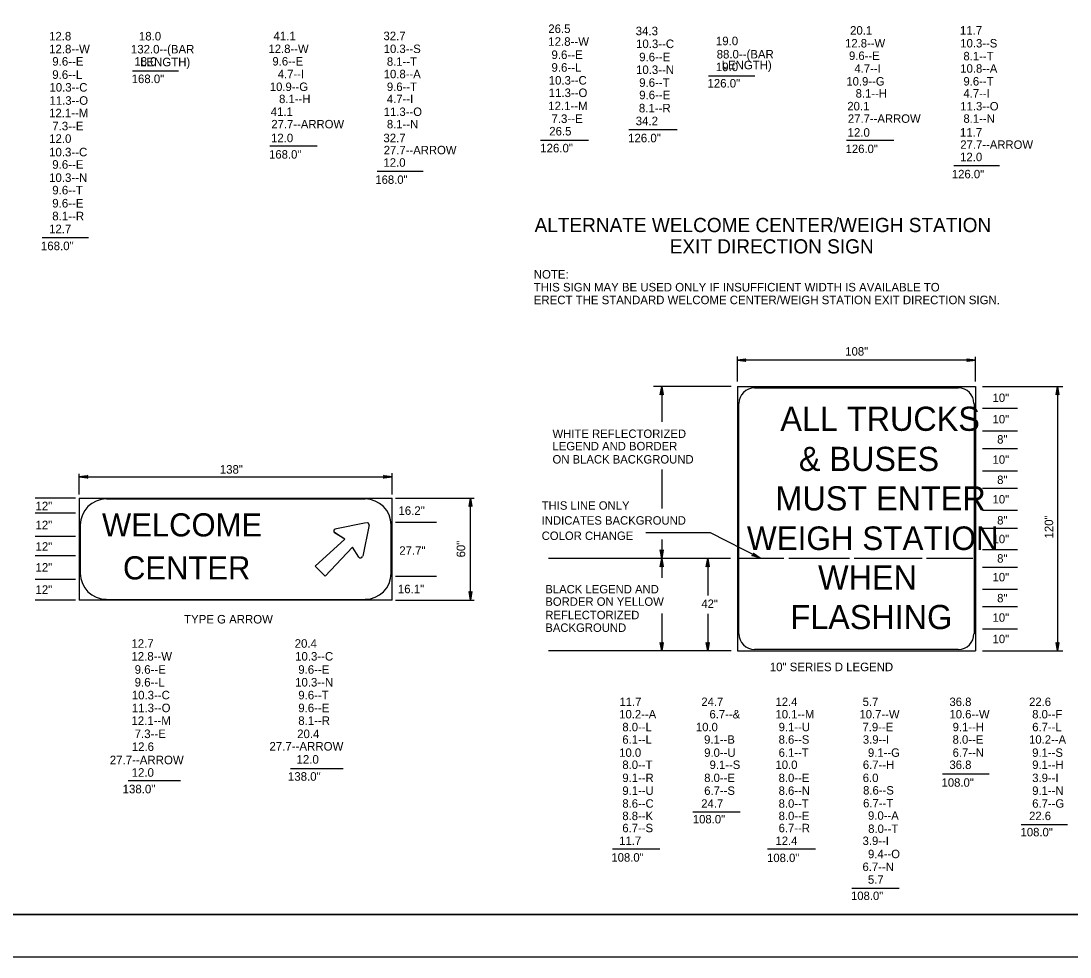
# Model space of a CAD drawing. Extents: x 2189973 to 2192941, y 2147557 to 2151454.
# Drawn here: x 2190680 to 2191890, y 2147557 to 2148636 of the extents above; entities that cross this region are included whole.
import ezdxf

# ---------------------------------------------------------------- set-up
doc = ezdxf.new("R2010")
doc.units = 0
for name, color, linetype in [('Default', 7, 'Continuous'), ('Level 2', 7, 'Continuous'), ('PLT-BNDY', 7, 'Continuous')]:
    doc.layers.add(name, color=color, linetype=linetype)

# ---------------------------------------------------------------- blocks, each defined once
blk = doc.blocks.new('RARROW')
at = {"layer": 'Default'}
blk.add_lwpolyline([(-18.156, 2.28), (-17.479, 0.966), (0, 0), (-18.156, 2.28), (-19.086, 3.077), (0, 0), (-17.465, -0.864), (-18.103, -2.164), (0, 0), (-19.086, -3.033), (-18.103, -2.164)], dxfattribs=at)

msp = doc.modelspace()

# ---------------------------------------------------------------- linework, layer by layer
at = {"layer": 'Default'}
for p, q in [((2190808.9, 2148579), (2190862.2, 2148579)), ((2191473.3, 2148573.2), (2191526.6, 2148573.2)), ((2191381.2, 2148511.3), (2191437, 2148511.3)), ((2190967.4, 2148492.5), (2191021.9, 2148492.5)), ((2191279.6, 2148499.1), (2191334.6, 2148499.1)), ((2191632.2, 2148498.9), (2191686.8, 2148498.9)), ((2191756.1, 2148469.7), (2191808.8, 2148469.7)), ((2191091.3, 2148463.4), (2191144, 2148463.4)), ((2190704.9, 2148386.8), (2190758.2, 2148386.8)), ((2190747.5, 2148090.3), (2190747.5, 2148114)), ((2190747.5, 2148110.7), (2191108.4, 2148110.7)), ((2191108.4, 2148090.3), (2191108.4, 2148114.8)), ((2190743.4, 2148086.2), (2190696.9, 2148086.2)), ((2190747.5, 2148086.2), (2191108.4, 2148086.2)), ((2190747.5, 2148086.2), (2190747.5, 2147968.5)), ((2191077.2, 2148085), (2190779.1, 2148085)), ((2191108.4, 2147968.5), (2191108.4, 2148086.2)), ((2191112.1, 2148086.2), (2191140.4, 2148086.2)), ((2191112.1, 2148086.2), (2191202.9, 2148086.2)), ((2191198.8, 2147968.5), (2191198.8, 2148086.2)), ((2190743.4, 2148068.6), (2190696.9, 2148068.6)), ((2191042.4, 2148050.5), (2191078.5, 2148057.9)), ((2191042.4, 2148050.5), (2191078.5, 2148057.9)), ((2191112.1, 2148058.3), (2191159.5, 2148058.3)), ((2190748.8, 2148055.1), (2190748.8, 2147999.3)), ((2191053.9, 2148038.7), (2191042, 2148046.4)), ((2191053.9, 2148038.7), (2191042, 2148046)), ((2191081.8, 2148055.1), (2191074.4, 2148019)), ((2191081.8, 2148055.1), (2191074.4, 2148019)), ((2191107.2, 2147999.3), (2191107.2, 2148055.1)), ((2190743.4, 2148041.9), (2190696.9, 2148041.9)), ((2191019.8, 2148007.5), (2191053.9, 2148038.7)), ((2191019.8, 2148007.5), (2191053.9, 2148038.7)), ((2191062.5, 2148029.6), (2191031.3, 2147996)), ((2191062.5, 2148029.6), (2191031.3, 2147996)), ((2191069.9, 2148018.1), (2191062.5, 2148029.6)), ((2191069.9, 2148018.1), (2191062.5, 2148029.6)), ((2190743.4, 2148019.4), (2190696.9, 2148019.4)), ((2191031.3, 2147996), (2191019.8, 2148007.5)), ((2191031.3, 2147996), (2191019.8, 2148007.5)), ((2190743.4, 2147992.3), (2190696.9, 2147992.3)), ((2191112.1, 2147996), (2191159.5, 2147996)), ((2190743.4, 2147968.5), (2190696.9, 2147968.5)), ((2191108.4, 2147968.5), (2190747.5, 2147968.5)), ((2190779.1, 2147969.3), (2191077.2, 2147969.3)), ((2191112.1, 2147968.5), (2191202.9, 2147968.5)), ((2190991.1, 2147774.4), (2191051.8, 2147774.4)), ((2190804.1, 2147760.3), (2190864.4, 2147760.3)), ((2192683.2, 2147606), (2190104.5, 2147606)), ((2190104.5, 2147606), (2192027, 2147606))]:
    msp.add_line(p, q, dxfattribs=at)
for centre, radius, start, end in [((2190778.8, 2148055.1), 30, 90, 180), ((2191077.2, 2148055.1), 30, 0, 90), ((2191079.5, 2148055.5), 2.25, 348.2602, 101.7398), ((2191079.5, 2148055.5), 2.25, 348.2602, 101.7398), ((2191043.3, 2148048), 2.25, 101.7398, 236.6838), ((2191043.3, 2148048), 2.25, 101.7398, 236.6838), ((2191071.9, 2148019.4), 2.25, 213.3162, 348.2602), ((2191071.9, 2148019.4), 2.25, 213.3162, 348.2602), ((2190778.8, 2147999.4), 30, 180, 270), ((2191077.2, 2147999.4), 30, 270, 0)]:
    msp.add_arc(centre, radius, start, end, dxfattribs=at)
at = {"layer": 'Level 2'}
for p, q in [((2191506.5, 2148220.7), (2191506.5, 2148249.4)), ((2191780.9, 2148245.3), (2191506.5, 2148245.3)), ((2191780.9, 2148220.7), (2191780.9, 2148249)), ((2191499.2, 2148215), (2191409.8, 2148215)), ((2191419.2, 2148215), (2191419.2, 2148174)), ((2191506.5, 2148215), (2191780.9, 2148215)), ((2191506.5, 2148215), (2191506.5, 2147909.9)), ((2191780.9, 2148215), (2191780.9, 2147909.9)), ((2191789.1, 2148215), (2191881.8, 2148215)), ((2191875.6, 2148215), (2191875.6, 2147909.9)), ((2191526.2, 2148213.4), (2191761.2, 2148213.4)), ((2191508.2, 2147929.6), (2191508.2, 2148195.3)), ((2191779.3, 2148195.3), (2191779.3, 2147929.6)), ((2191789.1, 2148190), (2191829.3, 2148190)), ((2191789.1, 2148163.7), (2191829.3, 2148163.7)), ((2191789.1, 2148143.2), (2191829.3, 2148143.2)), ((2191419.2, 2148119.2), (2191419.2, 2148074.3)), ((2191789.1, 2148117.4), (2191829.3, 2148117.4)), ((2191789.1, 2148097.7), (2191829.3, 2148097.7)), ((2191789.1, 2148072.3), (2191829.3, 2148072.3)), ((2191475.4, 2148046), (2191401, 2148046)), ((2191532.8, 2148016.9), (2191475.4, 2148046)), ((2191789.1, 2148051.4), (2191829.3, 2148051.4)), ((2191419.2, 2148038.3), (2191419.2, 2148016.5)), ((2191789.1, 2148026.8), (2191829.3, 2148026.8)), ((2191498.5, 2148016.5), (2191288.8, 2148016.5)), ((2191419.2, 2148016.5), (2191419.2, 2147994)), ((2191472.2, 2148016.5), (2191472.2, 2147973.9)), ((2191559.9, 2148016.5), (2191509, 2148016.5)), ((2191635.7, 2148016.5), (2191565.6, 2148016.5)), ((2191719.4, 2148016.5), (2191641.1, 2148016.5)), ((2191778, 2148016.5), (2191724.7, 2148016.5)), ((2191789.1, 2148006.3), (2191829.3, 2148006.3)), ((2191789.1, 2147981.2), (2191829.3, 2147981.2)), ((2191789.1, 2147961.1), (2191829.3, 2147961.1)), ((2191419.2, 2147952.9), (2191419.2, 2147909.9)), ((2191472.2, 2147952.5), (2191472.2, 2147909.9)), ((2191789.1, 2147935.3), (2191829.3, 2147935.3)), ((2191499.2, 2147909.9), (2191288.8, 2147909.9)), ((2191506.5, 2147909.9), (2191780.9, 2147909.9)), ((2191761.2, 2147911.5), (2191526.2, 2147911.5)), ((2191789.1, 2147909.9), (2191881.8, 2147909.9)), ((2191742.8, 2147768), (2191796.9, 2147768)), ((2191455, 2147724.4), (2191509.6, 2147724.4)), ((2191833.5, 2147709.7), (2191887, 2147709.7)), ((2191362.4, 2147681.5), (2191417, 2147681.5)), ((2191541.1, 2147681.5), (2191596.7, 2147681.5)), ((2191638.5, 2147636.3), (2191693.1, 2147636.3))]:
    msp.add_line(p, q, dxfattribs=at)
for centre, start, end in [((2191526.2, 2148195.3), 90, 180), ((2191761.2, 2148195.3), 0, 90), ((2191526.2, 2147929.6), 180, 270), ((2191761.2, 2147929.6), 270, 360)]:
    msp.add_arc(centre, 18, start, end, dxfattribs=at)
at = {"layer": 'PLT-BNDY'}
msp.add_lwpolyline([(2189973.2, 2149505.6), (2192732.4, 2149505.6), (2192732.4, 2147556.8), (2189973.2, 2147556.8)], close=True, dxfattribs=at)

# ---------------------------------------------------------------- block references
at = {"layer": 'Default', "xscale": 0.515679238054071, "yscale": 0.5369477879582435}
for p, rotation in [((2190747.5, 2148110.7), 180), ((2191198.8, 2148086.2), 89.99999999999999), ((2191198.8, 2147968.5), -90.00000000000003)]:
    msp.add_blockref('RARROW', p, dxfattribs=dict(at, rotation=rotation))
msp.add_blockref('RARROW', (2191108.4, 2148110.7), dxfattribs=at)
at = {"layer": 'Level 2', "xscale": 0.515679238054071, "yscale": 0.5369477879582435}
for p, rotation in [((2191506.5, 2148245.3), 180), ((2191419.2, 2148215), 89.99999999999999), ((2191875.6, 2148215), 89.99999999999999), ((2191419.2, 2148016.5), -90.00000000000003), ((2191532.8, 2148016.9), -26.538667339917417), ((2191419.2, 2148016.5), 89.99999999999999), ((2191472.2, 2148016.5), 89.99999999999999), ((2191419.2, 2147909.9), -90.00000000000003), ((2191472.2, 2147909.9), -90.00000000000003), ((2191875.6, 2147909.9), -90.00000000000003)]:
    msp.add_blockref('RARROW', p, dxfattribs=dict(at, rotation=rotation))
msp.add_blockref('RARROW', (2191780.9, 2148245.3), dxfattribs=at)

# ---------------------------------------------------------------- texts
at = {"layer": 'Default'}
for s, height, p in [('26.5   ', 9.84, (2191288.4, 2148622.6)), ('34.3   ', 9.89, (2191389.2, 2148620)), ('20.1      ', 9.84, (2191636.4, 2148620.7)), ('11.7       ', 9.842, (2191763.1, 2148620.7)), ('12.8   ', 9.84, (2190712.8, 2148614)), ('18.0               ', 9.842, (2190816.4, 2148614)), ('41.1      ', 9.84, (2190971.6, 2148614.3)), ('32.7       ', 9.842, (2191098.3, 2148614.3)), ('12.8--W', 9.89, (2191288.4, 2148607.8)), ('10.3--C', 9.84, (2191389.6, 2148605.2)), ('19.0               ', 9.842, (2191481.7, 2148608.5)), (' 12.8--W    ', 9.732, (2191627, 2148605.9)), ('10.3--S    ', 9.732, (2191763.5, 2148605.9)), ('12.8--W', 9.89, (2190712.8, 2148599.2)), ('132.0--(BAR', 9.842, (2190807.2, 2148599)), (' 12.8--W    ', 9.732, (2190962.2, 2148599.5)), ('10.3--S    ', 9.732, (2191098.7, 2148599.5)), (' 9.6--E', 9.89, (2191288.4, 2148592.6)), ('88.0--(BAR', 9.84, (2191482.6, 2148593.2)), ('  9.6--E     ', 9.732, (2191627.9, 2148591.5)), (' 9.6--E', 9.89, (2190712.8, 2148584.9)), (' 18.0               ', 9.842, (2190807.5, 2148584.9)), ('         LENGTH)', 9.842, (2190784.9, 2148584.2)), ('  9.6--E     ', 9.732, (2190963.1, 2148585.1)), (' 8.1--T    ', 9.732, (2191098.7, 2148584.8)), (' 9.6--E', 9.84, (2191389.6, 2148590)), ('         LENGTH)', 9.842, (2191455.4, 2148580.7)), (' 8.1--T    ', 9.732, (2191763.5, 2148591.1)), (' 9.6--L', 9.89, (2190712.8, 2148569.7)), (' 4.7--I    ', 9.732, (2190972.9, 2148570.4)), ('10.8--A    ', 9.732, (2191098.7, 2148570.4)), (' 9.6--L', 9.89, (2191288.4, 2148577.9)), ('10.3--N', 9.84, (2191389.6, 2148575.3)), ('19.0               ', 9.842, (2191481.7, 2148578.6)), (' 4.7--I    ', 9.732, (2191637.8, 2148576.8)), ('10.8--A    ', 9.732, (2191763.5, 2148576.8)), ('10.3--C', 9.84, (2190713.2, 2148555)), ('168.0"              ', 9.842, (2190808, 2148564.8)), (' 10.9--G    ', 9.732, (2190963.7, 2148555.7)), (' 9.6--T    ', 9.732, (2191098.7, 2148555.7)), ('10.3--C', 9.84, (2191288.9, 2148563.1)), (' 9.6--T', 9.84, (2191389.6, 2148560.5)), ('126.0"', 9.84, (2191472, 2148559.7)), (' 10.9--G    ', 9.732, (2191628.5, 2148562)), (' 9.6--T    ', 9.732, (2191763.5, 2148562)), ('11.3--O', 9.84, (2191288.9, 2148548.7)), (' 9.6--E', 9.84, (2191389.6, 2148546.2)), (' 8.1--H    ', 9.732, (2191639.2, 2148548.1)), (' 4.7--I    ', 9.732, (2191763.5, 2148548.1)), ('11.3--O', 9.84, (2190713.2, 2148539.8)), (' 8.1--H    ', 9.732, (2190974.4, 2148541.7)), (' 4.7--I    ', 9.732, (2191098.7, 2148541.7)), ('12.1--M', 9.84, (2191288.4, 2148533.6)), (' 8.1--R', 9.89, (2191389.2, 2148531)), (' 20.1       ', 9.842, (2191629.5, 2148533.3)), ('11.3--O    ', 9.732, (2191763.5, 2148533.3)), ('12.1--M', 9.84, (2190712.8, 2148525.4)), (' 41.1       ', 9.842, (2190964.7, 2148526.9)), ('11.3--O    ', 9.732, (2191098.7, 2148526.9)), (' 7.3--E', 9.89, (2191288.4, 2148518.8)), (' 27.7--ARROW', 9.732, (2191630.3, 2148519)), (' 8.1--N    ', 9.732, (2191763.5, 2148519)), (' 7.3--E', 9.89, (2190712.8, 2148510.3)), (' 27.7--ARROW', 9.732, (2190965.5, 2148512.6)), (' 8.1--N    ', 9.732, (2191098.7, 2148512.6)), ('34.2   ', 9.89, (2191389.2, 2148516.2)), ('12.0   ', 9.84, (2190712.9, 2148495.9)), (' 12.0       ', 9.842, (2190965, 2148496.6)), ('32.7       ', 9.842, (2191098.3, 2148496.6)), ('26.5', 9.84, (2191289.5, 2148504.4)), ('126.0"', 9.89, (2191380.4, 2148496.5)), (' 12.0       ', 9.842, (2191629.9, 2148503)), ('11.7       ', 9.842, (2191763.1, 2148503)), ('27.7--ARROW', 9.732, (2191098.7, 2148482.7)), ('126.0"   ', 9.89, (2191279.1, 2148484.9)), ('126.0"       ', 9.732, (2191631.3, 2148484.1)), ('27.7--ARROW', 9.732, (2191763.5, 2148489)), ('10.3--C', 9.89, (2190712.8, 2148480.3)), ('168.0"       ', 9.732, (2190966.5, 2148477.7)), ('12.0', 9.84, (2191763.2, 2148474.7)), (' 9.6--E', 9.89, (2190712.8, 2148466)), ('12.0', 9.84, (2191098.3, 2148468.3)), ('10.3--N', 9.89, (2190712.8, 2148450.8)), ('168.0"       ', 9.732, (2191089, 2148448.6)), ('126.0"       ', 9.732, (2191753.8, 2148455)), (' 9.6--T', 9.89, (2190712.8, 2148436.4)), (' 9.6--E', 9.89, (2190712.8, 2148421.3)), (' 8.1--R', 9.89, (2190712.8, 2148406.5)), ('ALTERNATE WELCOME CENTER/WEIGH STATION', 16.404, (2191272.6, 2148392.9)), ('12.7   ', 9.84, (2190712.8, 2148391.7)), ('EXIT DIRECTION SIGN', 16.404, (2191428.4, 2148368.3)), ('168.0"', 9.89, (2190703.4, 2148372.1)), ('NOTE:', 9.84, (2191271.7, 2148339.3)), ('THIS SIGN MAY BE USED ONLY IF INSUFFICIENT WIDTH IS AVAILABLE TO ', 9.842, (2191271.7, 2148324.5)), ('ERECT THE STANDARD WELCOME CENTER/WEIGH STATION EXIT DIRECTION SIGN.', 9.842, (2191271.7, 2148309.8)), ('138"', 9.84, (2190909.7, 2148114.3)), ('12"', 9.84, (2190697.2, 2148072.1)), ('16.2"', 9.84, (2191115.7, 2148066.8)), ('12"', 9.84, (2190697.2, 2148050.2)), ('12"', 9.84, (2190697.2, 2148025.4)), ('27.7"', 9.84, (2191116.6, 2148020.7)), ('12"', 9.84, (2190697.2, 2148001.3)), ('12"', 9.84, (2190697.2, 2147975.7)), ('16.1"', 9.84, (2191115, 2147976.4)), ('TYPE G ARROW', 9.842, (2190868.5, 2147941.5)), ('12.7   ', 9.84, (2190807.8, 2147913.5)), ('20.4   ', 9.84, (2190996, 2147913.5)), ('12.8--W', 9.84, (2190807.8, 2147898.7)), ('10.3--C', 9.84, (2190996.5, 2147898.7)), (' 9.6--E', 9.89, (2190807.8, 2147883.5)), (' 9.6--E', 9.84, (2190996.5, 2147883.5)), (' 9.6--L', 9.89, (2190807.8, 2147868.8)), ('10.3--N', 9.84, (2190996.5, 2147868.8)), ('10.3--C', 9.84, (2190808.2, 2147854)), (' 9.6--T', 9.84, (2190996.5, 2147854)), ('11.3--O', 9.84, (2190808.2, 2147839.2)), (' 9.6--E', 9.84, (2190996.5, 2147839.2)), ('12.1--M', 9.84, (2190807.8, 2147824.5)), (' 8.1--R', 9.84, (2190996.5, 2147824.5)), (' 7.3--E', 9.89, (2190807.8, 2147809.3)), ('20.4  ', 9.84, (2190998.9, 2147809.3)), ('12.6  ', 9.84, (2190808.2, 2147794.5)), ('     27.7--ARROW', 9.894, (2190948.5, 2147794.9)), ('    27.7--ARROW', 9.894, (2190768.1, 2147779.1)), ('12.0   ', 9.89, (2190998.1, 2147779.8)), ('12.0   ', 9.89, (2190808, 2147764.7)), ('138.0"   ', 9.89, (2190988.2, 2147760.1)), ('138.0"   ', 9.89, (2190797.6, 2147745.6))]:
    msp.add_text(s, height=height, dxfattribs=at).set_placement(p)
for s, height, rotation, p in [('WELCOME', 26.72, 360, (2190773.8, 2148041.9)), ('60"', 9.84, 90, (2191192.6, 2148017.7)), ('CENTER', 26.72, 360, (2190798, 2147992.3))]:
    msp.add_text(s, height=height, rotation=rotation, dxfattribs=at).set_placement(p)
at = {"layer": 'Level 2'}
for s, height, p in [('108"', 9.73, (2191630.9, 2148250.5)), ('10"', 9.73, (2191800.7, 2148197)), ('10"', 9.73, (2191800.7, 2148172.3)), ('WHITE REFLECTORIZED', 9.732, (2191293.3, 2148155.5)), ('8"', 9.73, (2191806, 2148149)), ('LEGEND AND BORDER', 9.732, (2191293.3, 2148141.2)), ('ON BLACK BACKGROUND', 9.732, (2191293.3, 2148126)), ('10"', 9.73, (2191800.7, 2148125.7)), ('8"', 9.73, (2191806, 2148102.4)), ('THIS LINE ONLY', 9.732, (2191280.8, 2148072.7)), ('10"', 9.73, (2191800.7, 2148079.9)), ('INDICATES BACKGROUND', 9.732, (2191280.8, 2148055.5)), ('8"', 9.73, (2191806, 2148055.7)), ('COLOR CHANGE', 9.732, (2191280.8, 2148037.8)), ('10"', 9.73, (2191800.7, 2148034.1)), ('8"', 9.73, (2191806, 2148011.7)), ('10"', 9.73, (2191800.7, 2147990.1)), ('BLACK LEGEND AND', 9.732, (2191285, 2147976.2)), ('8"', 9.73, (2191806, 2147965.9)), ('BORDER ON YELLOW', 9.732, (2191285, 2147961.9)), ('42"', 9.73, (2191464.9, 2147959.4)), ('REFLECTORIZED ', 9.732, (2191285, 2147946.4)), ('10"', 9.73, (2191800.7, 2147943.5)), ('BACKGROUND', 9.73, (2191285, 2147931.8)), ('10"', 9.73, (2191800.7, 2147918.8)), (' 10" SERIES D LEGEND', 9.842, (2191540.2, 2147886.5)), ('11.7    ', 9.73, (2191370.5, 2147846.3)), ('24.7    ', 9.73, (2191464.9, 2147846.3)), ('12.4   ', 9.73, (2191550.4, 2147846.3)), (' 5.7', 9.73, (2191647.3, 2147846.3)), ('36.8   ', 9.73, (2191751, 2147846.3)), ('22.6   ', 9.73, (2191842.8, 2147846.3)), ('10.2--A', 9.73, (2191370.2, 2147832)), ('6.7--&', 9.73, (2191474.3, 2147832)), ('10.1--M', 9.73, (2191550.4, 2147832)), ('10.7--W', 9.73, (2191647.2, 2147832)), ('10.6--W', 9.73, (2191751, 2147832)), (' 8.0--F', 9.73, (2191842.8, 2147832)), (' 8.0--L', 9.73, (2191370.2, 2147817.2)), (' 10.0', 9.73, (2191455, 2147817.2)), (' 9.1--U', 9.73, (2191550.4, 2147817.2)), (' 7.9--E', 9.73, (2191647.1, 2147817.2)), (' 9.1--H', 9.73, (2191751, 2147817.2)), (' 6.7--L', 9.73, (2191842.8, 2147817.2)), (' 6.1--L', 9.73, (2191370.2, 2147802.8)), (' 9.1--B', 9.73, (2191464.5, 2147802.8)), (' 8.6--S', 9.73, (2191550.4, 2147802.8)), (' 3.9--I', 9.73, (2191647.5, 2147802.8)), (' 8.0--E', 9.73, (2191751, 2147802.8)), ('10.2--A', 9.73, (2191842.8, 2147802.8)), ('10.0   ', 9.73, (2191370.2, 2147787.7)), (' 9.0--U   ', 9.73, (2191464.6, 2147787.7)), (' 6.1--T', 9.73, (2191550.4, 2147787.7)), ('9.1--G', 9.73, (2191657, 2147787.7)), (' 6.7--N', 9.73, (2191751, 2147787.7)), (' 9.1--S', 9.73, (2191842.8, 2147787.7)), (' 8.0--T', 9.73, (2191370.2, 2147773.7)), ('9.1--S', 9.73, (2191474.4, 2147773.7)), ('10.0   ', 9.73, (2191550.4, 2147773.7)), (' 6.7--H', 9.73, (2191647.5, 2147773.7)), ('36.8   ', 9.73, (2191751, 2147773.7)), (' 9.1--H', 9.73, (2191842.8, 2147773.7)), (' 9.1--R', 9.73, (2191370.2, 2147758.6)), (' 8.0--E', 9.73, (2191464.6, 2147758.6)), (' 8.0--E', 9.73, (2191550.4, 2147758.6)), (' 6.0   ', 9.73, (2191647.4, 2147758.6)), (' 3.9--I', 9.73, (2191842.8, 2147758.6)), ('108.0"', 9.73, (2191741.9, 2147753.2)), (' 9.1--U', 9.73, (2191370.2, 2147743.8)), (' 6.7--S', 9.73, (2191464.6, 2147743.8)), (' 8.6--N', 9.73, (2191550.4, 2147743.8)), (' 8.6--S', 9.73, (2191647.8, 2147744.2)), (' 9.1--N', 9.73, (2191842.8, 2147743.8)), (' 8.6--C', 9.73, (2191370.2, 2147729)), ('24.7', 9.73, (2191464.8, 2147729)), (' 8.0--T', 9.73, (2191550.4, 2147729)), (' 6.7--T', 9.73, (2191647.8, 2147729.4)), (' 6.7--G', 9.73, (2191842.8, 2147729)), (' 8.8--K', 9.73, (2191370.2, 2147714.7)), ('108.0" ', 9.73, (2191455.1, 2147710.9)), (' 8.0--E', 9.73, (2191550.4, 2147714.7)), ('9.0--A', 9.73, (2191657.1, 2147715.1)), ('22.6   ', 9.73, (2191842.8, 2147714.7)), (' 6.7--S', 9.73, (2191370.2, 2147700.7)), (' 6.7--R', 9.73, (2191550.4, 2147700.7)), ('8.0--T', 9.73, (2191657.3, 2147699.9)), ('11.7   ', 9.73, (2191370.2, 2147686)), ('12.4   ', 9.73, (2191550.4, 2147686)), (' 3.9--I', 9.73, (2191647.2, 2147686)), ('108.0"', 9.73, (2191833, 2147696)), ('108.0" ', 9.73, (2191361.2, 2147666.8)), ('108.0"', 9.73, (2191540.7, 2147666.3)), ('9.4--O', 9.73, (2191657.1, 2147670.8)), (' 6.7--N', 9.73, (2191647.1, 2147656)), ('5.7   ', 9.73, (2191657, 2147641.3)), ('108.0"', 9.73, (2191637.5, 2147622.5))]:
    msp.add_text(s, height=height, dxfattribs=at).set_placement(p)
for s, height, rotation, p in [('ALL TRUCKS', 27.89, 360, (2191556, 2148163.7)), ('& BUSES', 27.89, 360, (2191577.4, 2148117.4)), ('MUST ENTER', 27.89, 360, (2191550.4, 2148071.9)), ('120"', 9.84, 90, (2191870.6, 2148039.6)), ('WEIGH STATION', 27.129, 360, (2191517.5, 2148026.3)), ('WHEN', 27.89, 360, (2191599.5, 2147980.6)), ('FLASHING', 27.89, 360, (2191567.7, 2147935))]:
    msp.add_text(s, height=height, rotation=rotation, dxfattribs=at).set_placement(p)

doc.saveas('drawing.dxf')
